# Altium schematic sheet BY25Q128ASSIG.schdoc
size 127 x 101 mm
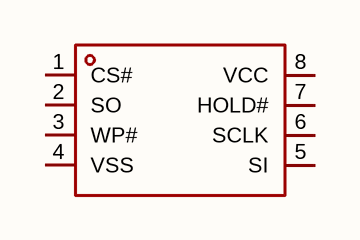
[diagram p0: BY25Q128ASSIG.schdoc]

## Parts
U?  by25q128assig(r)  [SOP-8_L5.3-W5.3-P1.27-LS8.0-BL]  (value not drawn)

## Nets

Not connected (* = marked no-connect by the designer): U? 1(CS#) 2(SO) 3(WP#) 4(VSS) 5(SI) 6(SCLK) 7(HOLD#) 8(VCC)

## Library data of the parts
U? = by25q128assig(r): Manufacturer: BOYAMICRO(博雅); AddInBom: yes; ModelId: e456afcfff5840a795bdd4917416584f; ModelName: SOP-8_L5.2-W5.3-H2.1-LS7.9-P1.27; ModelTransform: 311.024,204.724,0,90,0,0,0,0.0005,0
